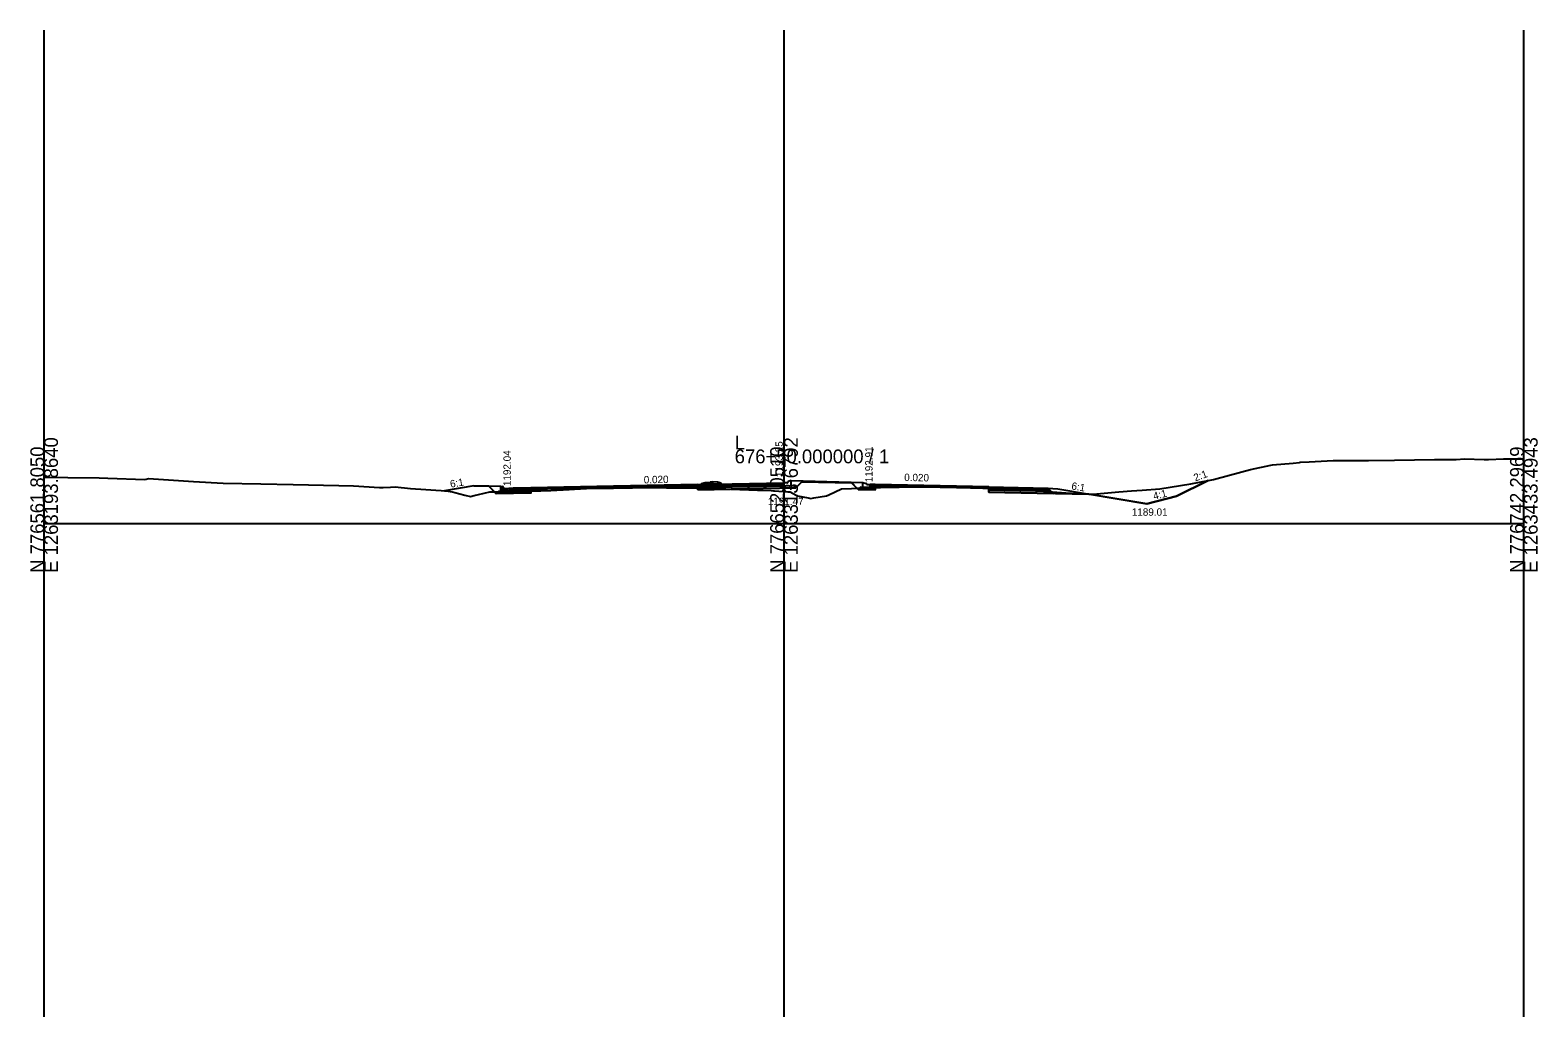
# Model space of a CAD drawing. Extents: x -41 to 1262860, y -100 to 777489.
# Drawn here: x 497.2 to 802.8, y 1605 to 1805 of the extents above; entities that cross this region are included whole.
import ezdxf

# ---------------------------------------------------------------- set-up
doc = ezdxf.new("R2010")
doc.units = 0
for name, color, linetype in [('Exist Cross Section Cell', 7, 'Continuous'), ('Exist XS Center Line Elevation Label', 7, 'Continuous'), ('Exist XS Ground Line', 7, 'Continuous'), ('Prop CMT Pvmt Course 1', 7, 'Continuous'), ('Prop CMT Pvmt Course 4', 7, 'Continuous'), ('Prop CMT Pvmt Surface', 7, 'Continuous'), ('Prop CMT Shld Paved Course 1', 7, 'Continuous'), ('Prop CMT Shld Paved Course 2', 7, 'Continuous'), ('Prop CMT Shld Paved Course 4', 7, 'Continuous'), ('Prop CMT Subgrade Earthwork', 7, 'Continuous'), ('Prop Conc Curb and Gutter', 7, 'Continuous'), ('Prop Conc Island Cover', 7, 'Continuous'), ('Prop XS Ditch Standard Text', 7, 'Continuous'), ('Prop XS Earthwork Shape', 7, 'Continuous'), ('Prop XS Elevation Labels', 7, 'Continuous'), ('Prop XS Exc Vertical Line 1', 7, 'Continuous'), ('Prop XS Exc Vertical Line 2', 7, 'Continuous'), ('Prop XS Exc Vertical Line 3', 7, 'Continuous'), ('Prop XS Finish Grade', 7, 'Continuous'), ('Prop XS Finish Grade Earthwork', 7, 'Continuous'), ('Prop XS Hydro Elevations', 7, 'Continuous'), ('Prop XS SE Text', 7, 'Continuous'), ('Prop XS Side Slope Text', 7, 'Continuous'), ('Scratch_Level_4', 7, 'Continuous'), ('Scratch_Level_6', 7, 'Continuous'), ('Typical Curb CELL', 7, 'Continuous')]:
    doc.layers.add(name, color=color, linetype=linetype)

msp = doc.modelspace()

# ---------------------------------------------------------------- linework, layer by layer
at = {"layer": 'Exist Cross Section Cell'}
for p, q in [((650, 1705), (650, 1720)), ((500, 1705), (650, 1705)), ((650, 1705), (800, 1705))]:
    msp.add_line(p, q, dxfattribs=at)
at = {"layer": 'Exist XS Ground Line'}
msp.add_lwpolyline([(500, 1714.36), (500.81, 1714.36), (504.81, 1714.32), (511.14, 1714.27), (512.93, 1714.2), (520.39, 1713.91), (520.65, 1713.98), (521.15, 1714.12), (530.28, 1713.48), (536.28, 1713.2), (543.91, 1713.04), (550.49, 1712.9), (559.73, 1712.67), (562.71, 1712.64), (568.02, 1712.33), (568.76, 1712.32), (570.23, 1712.39), (571.19, 1712.42), (574.24, 1712.07), (581.51, 1711.62), (582.69, 1711.43), (583.26, 1711.25), (585.31, 1710.74), (586.42, 1710.48), (587.2, 1710.66), (588.08, 1710.88), (590.35, 1711.42), (592.04, 1711.41), (592.94, 1711.39), (593.26, 1711.38), (593.33, 1711.39), (594.01, 1711.41), (598.77, 1711.58), (602.72, 1711.7), (606.45, 1711.87), (607.51, 1711.93), (611.2, 1712.13), (613.45, 1712.17), (623.15, 1712.3), (626.17, 1712.26), (635, 1712.15), (644.65, 1711.78), (647.42, 1711.67), (647.9, 1711.62), (648.06, 1711.6), (650.79, 1711.41), (651.23, 1711.4), (652.49, 1710.74), (652.75, 1710.61), (654.93, 1710.18), (655.47, 1710.08), (656.07, 1710.18), (658.63, 1710.61), (659.09, 1710.83), (661.68, 1712.01), (663.66, 1712.11), (665.82, 1712.22), (673.38, 1712.36), (678.34, 1712.46), (685.26, 1712.32), (690.31, 1712.23), (690.38, 1712.38), (692.66, 1712.25), (702.6, 1711.55), (707.16, 1711.2), (707.82, 1711.17), (708.28, 1711.16), (711.32, 1710.98), (712.69, 1710.94), (717.87, 1711.4), (720.47, 1711.62), (722.65, 1711.79), (726.21, 1712), (732.45, 1713.01), (737.08, 1713.94), (740.33, 1714.81), (744.55, 1715.95), (748.69, 1716.83), (749.02, 1716.86), (753.23, 1717.26), (754.52, 1717.39), (754.59, 1717.4), (754.67, 1717.42), (754.75, 1717.43), (756.45, 1717.49), (761.36, 1717.75), (761.56, 1717.75), (768.53, 1717.78), (773.75, 1717.87), (781.9, 1717.95), (786.25, 1717.99), (787.99, 1718.12), (791.97, 1717.99), (792.83, 1718), (795.85, 1718.12), (797.4, 1718.14), (799.66, 1718.13), (800, 1718.13)], dxfattribs=at)
at = {"layer": 'Prop CMT Pvmt Course 1'}
for p, q in [((595.12, 1711.9), (595.11, 1712.15)), ((598.68, 1711.97), (595.12, 1711.9)), ((632.5, 1712.65), (649.97, 1713)), ((649.97, 1713), (649.97, 1713.25)), ((667.5, 1712.9), (667.5, 1712.65)), ((668.5, 1712.63), (667.5, 1712.65))]:
    msp.add_line(p, q, dxfattribs=at)
for points in [[(598.68, 1712.22), (598.68, 1711.97), (598.68, 1711.97), (615.45, 1712.3), (615.45, 1712.3), (615.45, 1712.3), (632.5, 1712.65), (632.5, 1712.9), (632.5, 1712.9), (615.45, 1712.55), (615.45, 1712.55), (615.45, 1712.55), (598.68, 1712.22), (598.68, 1712.22), (598.68, 1712.22)], [(691.5, 1712.42), (691.5, 1712.42), (668.5, 1712.88), (668.5, 1712.88), (668.5, 1712.88), (668.5, 1712.88), (668.5, 1712.88), (668.5, 1712.63), (668.5, 1712.63), (668.5, 1712.63), (668.5, 1712.63), (691.5, 1712.17), (691.5, 1712.42)]]:
    msp.add_lwpolyline(points, dxfattribs=at)
at = {"layer": 'Prop CMT Pvmt Course 4'}
for p, q in [((592.12, 1711.5), (591.66, 1711.04)), ((598.68, 1711.18), (591.66, 1711.04)), ((592.62, 1711.51), (592.12, 1711.5)), ((598.68, 1711.18), (598.68, 1711.64))]:
    msp.add_line(p, q, dxfattribs=at)
at = {"layer": 'Prop CMT Pvmt Surface'}
for p, q in [((598.68, 1712.22), (595.11, 1712.15)), ((598.68, 1712.22), (632.5, 1712.9)), ((632.5, 1712.9), (649.97, 1713.25)), ((668.5, 1712.88), (667.5, 1712.9)), ((668.5, 1712.88), (691.5, 1712.42)), ((691.5, 1712.42), (703.5, 1712.18))]:
    msp.add_line(p, q, dxfattribs=at)
at = {"layer": 'Prop CMT Shld Paved Course 1'}
for p, q in [((691.5, 1712.42), (691.5, 1712.42)), ((691.5, 1712.42), (691.5, 1712.42)), ((691.5, 1712.42), (691.5, 1712.17)), ((691.5, 1712.17), (691.5, 1712.17)), ((691.5, 1712.17), (703.76, 1711.92)), ((695.5, 1712.34), (695.5, 1712.34)), ((703.76, 1711.92), (703.5, 1712.18))]:
    msp.add_line(p, q, dxfattribs=at)
at = {"layer": 'Prop CMT Shld Paved Course 2'}
for p, q in [((595.12, 1711.56), (595.12, 1711.9)), ((598.77, 1711.97), (598.68, 1711.97)), ((598.68, 1711.97), (598.68, 1711.97)), ((598.68, 1711.97), (598.68, 1711.64)), ((602.72, 1712.05), (598.77, 1711.97)), ((598.77, 1711.97), (598.77, 1711.97)), ((606.45, 1712.12), (602.72, 1712.05)), ((603.29, 1711.73), (606.45, 1711.87)), ((607.51, 1712.15), (606.45, 1712.12)), ((606.45, 1712.12), (606.45, 1712.12)), ((606.45, 1711.87), (607.51, 1711.93)), ((606.45, 1711.87), (606.45, 1711.87)), ((611.2, 1712.22), (607.51, 1712.15)), ((607.51, 1712.15), (607.51, 1712.15)), ((607.51, 1711.93), (611.2, 1712.13)), ((607.51, 1711.93), (607.51, 1711.93)), ((613.45, 1712.26), (611.2, 1712.22)), ((611.2, 1712.22), (611.2, 1712.22)), ((611.2, 1712.13), (613.45, 1712.17)), ((611.2, 1712.13), (611.2, 1712.13)), ((615.45, 1712.3), (613.45, 1712.26)), ((613.45, 1712.26), (613.45, 1712.26)), ((613.45, 1712.17), (615.45, 1712.19)), ((613.45, 1712.17), (613.45, 1712.17)), ((623.15, 1712.46), (615.45, 1712.3)), ((615.45, 1712.19), (623.15, 1712.3)), ((626.17, 1712.52), (623.15, 1712.46)), ((623.15, 1712.46), (623.15, 1712.46)), ((623.15, 1712.46), (623.15, 1712.46)), ((623.15, 1712.3), (623.15, 1712.3)), ((623.15, 1712.3), (623.15, 1712.3)), ((623.15, 1712.3), (626.17, 1712.26)), ((632.5, 1712.65), (626.17, 1712.52)), ((626.17, 1712.52), (626.17, 1712.52)), ((626.17, 1712.52), (626.17, 1712.52)), ((626.17, 1712.26), (626.17, 1712.26)), ((626.17, 1712.26), (628.42, 1712.23)), ((628.42, 1712.23), (632.5, 1712.31)), ((632.5, 1712.31), (649.97, 1712.66)), ((632.5, 1712.31), (632.5, 1712.65)), ((632.5, 1712.65), (632.5, 1712.65)), ((632.5, 1712.31), (632.5, 1712.31)), ((649.97, 1713), (649.97, 1712.66)), ((667.5, 1712.31), (667.5, 1712.65)), ((668.5, 1712.29), (667.5, 1712.31)), ((668.5, 1712.29), (668.5, 1712.63)), ((668.5, 1712.63), (668.5, 1712.63)), ((668.5, 1712.63), (668.5, 1712.63)), ((668.5, 1712.63), (668.5, 1712.63)), ((668.5, 1712.63), (673.38, 1712.53)), ((669.01, 1712.28), (668.5, 1712.29)), ((668.5, 1712.29), (668.5, 1712.29)), ((668.5, 1712.29), (668.5, 1712.29)), ((673.38, 1712.36), (669.01, 1712.28)), ((669.01, 1712.28), (669.01, 1712.28)), ((673.38, 1712.53), (673.38, 1712.53)), ((673.38, 1712.53), (678.34, 1712.43)), ((677.51, 1712.45), (673.38, 1712.36)), ((673.38, 1712.36), (673.38, 1712.36)), ((678.34, 1712.43), (677.51, 1712.45)), ((677.51, 1712.45), (677.51, 1712.45)), ((685.26, 1712.29), (678.34, 1712.43)), ((678.34, 1712.43), (685.26, 1712.29)), ((690.31, 1712.19), (685.26, 1712.29)), ((685.26, 1712.29), (685.26, 1712.29)), ((685.26, 1712.29), (685.26, 1712.29)), ((685.26, 1712.29), (690.31, 1712.19)), ((690.38, 1712.19), (690.31, 1712.19)), ((690.31, 1712.19), (690.31, 1712.19)), ((690.31, 1712.19), (690.31, 1712.19)), ((690.31, 1712.19), (690.38, 1712.19)), ((691.5, 1712.17), (690.38, 1712.19)), ((690.38, 1712.19), (690.38, 1712.19)), ((690.38, 1712.19), (690.38, 1712.19)), ((690.38, 1712.19), (691.5, 1712.17)), ((691.5, 1712.17), (691.5, 1712.17)), ((691.5, 1712.17), (691.5, 1712.17)), ((691.5, 1712.17), (691.5, 1711.83)), ((691.5, 1712.17), (691.5, 1712.17)), ((691.5, 1712.17), (691.5, 1712.17)), ((691.5, 1711.83), (691.5, 1711.83)), ((691.5, 1711.83), (704.1, 1711.58)), ((695.76, 1712.08), (695.76, 1712.08)), ((704.1, 1711.58), (703.76, 1711.92)), ((598.68, 1711.64), (595.12, 1711.56)), ((598.68, 1711.64), (598.77, 1711.64)), ((598.77, 1711.64), (602.72, 1711.72)), ((598.77, 1711.64), (598.77, 1711.64)), ((602.72, 1711.72), (603.29, 1711.73)), ((602.72, 1711.72), (602.72, 1711.72))]:
    msp.add_line(p, q, dxfattribs=at)
at = {"layer": 'Prop CMT Shld Paved Course 4'}
for p, q in [((628.42, 1712.23), (632.5, 1712.18)), ((632.5, 1711.85), (632.5, 1712.31)), ((632.5, 1711.85), (652.42, 1712.25)), ((649.97, 1712.66), (651.97, 1712.7)), ((651.97, 1712.7), (652.42, 1712.25)), ((665.5, 1712.35), (665.05, 1711.9)), ((668.5, 1711.83), (665.05, 1711.9)), ((667.5, 1712.31), (665.5, 1712.35)), ((668.5, 1711.83), (668.5, 1712.29)), ((669.01, 1712.28), (668.5, 1712.27)), ((691.5, 1711.83), (691.5, 1711.83)), ((691.5, 1711.83), (691.5, 1711.83)), ((691.5, 1711.83), (691.5, 1711.37)), ((598.77, 1711.58), (598.68, 1711.58)), ((598.77, 1711.58), (602.72, 1711.7)), ((603.29, 1711.73), (602.72, 1711.7)), ((691.5, 1711.37), (704.56, 1711.11)), ((696.1, 1711.74), (696.1, 1711.74)), ((696.6, 1711.73), (696.6, 1711.73)), ((704.56, 1711.11), (704.1, 1711.58))]:
    msp.add_line(p, q, dxfattribs=at)
at = {"layer": 'Prop CMT Subgrade Earthwork'}
for p, q in [((591.66, 1711.04), (590.13, 1712.56)), ((632.5, 1711.85), (652.42, 1712.25)), ((632.5, 1711.85), (632.5, 1712.18)), ((652.42, 1712.25), (653.81, 1713.64)), ((665.05, 1711.9), (663.55, 1713.4)), ((665.05, 1711.9), (668.5, 1711.83)), ((668.5, 1711.83), (668.5, 1712.27)), ((691.5, 1712.32), (691.5, 1711.37)), ((598.68, 1711.18), (591.66, 1711.04)), ((598.68, 1711.58), (598.68, 1711.18)), ((691.5, 1711.37), (711.78, 1710.97))]:
    msp.add_line(p, q, dxfattribs=at)
at = {"layer": 'Prop Conc Curb and Gutter'}
for p, q in [((633.25, 1712.91), (633.26, 1713.08)), ((633.25, 1712.91), (633.25, 1712.91)), ((633.25, 1712.91), (633.25, 1712.79)), ((635.01, 1712.91), (633.25, 1712.91)), ((633.25, 1712.91), (633.25, 1712.91)), ((633.25, 1712.79), (633.25, 1712.79)), ((633.25, 1712.79), (635.01, 1712.79)), ((633.26, 1713.08), (634.01, 1713.33)), ((633.26, 1713.08), (633.26, 1713.08)), ((634.01, 1713.33), (635.01, 1713.35)), ((634.01, 1713.33), (634.01, 1713.33)), ((635.01, 1713.35), (635.01, 1712.91)), ((635.01, 1712.79), (635.01, 1712.91)), ((635.01, 1712.91), (635.01, 1712.91)), ((635.01, 1712.79), (635.01, 1712.79)), ((635.01, 1712.79), (635.01, 1712.79)), ((636.49, 1713.41), (635.49, 1713.43)), ((635.49, 1713.43), (635.49, 1712.99)), ((637.25, 1712.99), (635.49, 1712.99)), ((635.49, 1712.99), (635.49, 1712.87)), ((635.49, 1712.99), (635.49, 1712.99)), ((635.49, 1712.87), (635.49, 1712.87)), ((635.49, 1712.87), (637.25, 1712.87)), ((637.24, 1713.16), (636.49, 1713.41)), ((636.49, 1713.41), (636.49, 1713.41)), ((637.25, 1712.99), (637.24, 1713.16)), ((637.24, 1713.16), (637.24, 1713.16)), ((637.25, 1712.87), (637.25, 1712.99)), ((637.25, 1712.99), (637.25, 1712.99)), ((637.25, 1712.99), (637.25, 1712.99)), ((637.25, 1712.87), (637.25, 1712.87)), ((637.25, 1712.87), (637.25, 1712.87)), ((650.66, 1713.26), (649.97, 1713.25)), ((649.97, 1713.25), (649.97, 1712.66)), ((649.97, 1712.66), (651.47, 1712.69)), ((650.72, 1713.34), (650.72, 1713.32)), ((651.47, 1713.69), (650.82, 1713.48)), ((651.47, 1712.69), (651.47, 1713.69)), ((651.47, 1712.69), (651.47, 1712.69)), ((666, 1713.34), (666.65, 1713.13)), ((666, 1712.34), (666, 1713.34)), ((667.5, 1712.31), (666, 1712.34)), ((666.75, 1712.99), (666.75, 1712.97)), ((666.81, 1712.91), (667.5, 1712.9)), ((667.5, 1712.31), (667.5, 1712.9))]:
    msp.add_line(p, q, dxfattribs=at)
for centre, radius, start, end in [((650.66, 1713.32), 0.0625, 271.1458, 360), ((650.87, 1713.34), 0.146, 108.435, 180), ((666.6, 1712.99), 0.146, 0, 71.565), ((666.81, 1712.97), 0.0625, 180, 268.8542)]:
    msp.add_arc(centre, radius, start, end, dxfattribs=at)
at = {"layer": 'Prop Conc Island Cover'}
for p, q in [((635.49, 1713.43), (635.01, 1713.35)), ((635.01, 1713.35), (635.01, 1713.1)), ((635.49, 1713.17), (635.01, 1713.09)), ((635.49, 1713.18), (635.49, 1713.43)), ((635.49, 1713.43), (635.49, 1713.43)), ((635.49, 1713.18), (635.49, 1713.18)), ((651.47, 1713.69), (666, 1713.34)), ((651.47, 1713.43), (651.47, 1713.43))]:
    msp.add_line(p, q, dxfattribs=at)
at = {"layer": 'Prop XS Earthwork Shape'}
for points in [[(586.42, 1710.48), (587.2, 1710.66), (588.08, 1710.88), (590.35, 1711.42), (591.28, 1711.42), (590.13, 1712.56), (587.1, 1712.62), (581.18, 1711.64), (581.51, 1711.62), (582.69, 1711.43), (583.26, 1711.25), (585.31, 1710.74)], [(632.5, 1711.85), (632.5, 1712.18), (635, 1712.15), (639.26, 1711.99)], [(663.66, 1712.11), (664.78, 1712.17), (663.81, 1713.15), (653.56, 1713.39), (652.42, 1712.25), (639.26, 1711.99), (644.65, 1711.78), (647.42, 1711.67), (647.9, 1711.62), (648.06, 1711.6), (650.79, 1711.41), (651.23, 1711.4), (652.49, 1710.74), (652.75, 1710.61), (654.93, 1710.18), (655.47, 1710.08), (656.07, 1710.18), (658.63, 1710.61), (659.09, 1710.83), (661.68, 1712.01)], [(665.05, 1711.9), (664.78, 1712.17), (665.82, 1712.22), (668.5, 1712.27), (668.5, 1711.83)], [(702.6, 1711.55), (704.25, 1711.42), (704.56, 1711.11), (691.5, 1711.37), (691.5, 1712.32), (692.66, 1712.25)], [(720.47, 1711.62), (722.65, 1711.79), (726.21, 1712), (732.45, 1713.01), (736.03, 1713.73), (729.6, 1710.52), (723.56, 1709.01), (711.78, 1710.97), (712.69, 1710.94), (717.87, 1711.4)], [(593.33, 1711.39), (594.01, 1711.41), (598.68, 1711.58), (598.68, 1711.18), (591.66, 1711.04), (591.28, 1711.42), (592.04, 1711.41), (592.94, 1711.39), (593.26, 1711.38)], [(707.82, 1711.17), (708.28, 1711.16), (711.32, 1710.98), (711.78, 1710.97), (704.56, 1711.11), (704.25, 1711.42), (707.16, 1711.2)]]:
    msp.add_lwpolyline(points, close=True, dxfattribs=at)
at = {"layer": 'Prop XS Exc Vertical Line 1'}
msp.add_line((500, 1605), (500, 1805), dxfattribs=at)
at = {"layer": 'Prop XS Exc Vertical Line 2'}
msp.add_line((650, 1605), (650, 1805), dxfattribs=at)
at = {"layer": 'Prop XS Exc Vertical Line 3'}
msp.add_line((800, 1605), (800, 1805), dxfattribs=at)
at = {"layer": 'Prop XS Finish Grade'}
for p, q in [((587.1, 1712.62), (581.18, 1711.64)), ((587.1, 1712.62), (590.13, 1712.56)), ((703.5, 1712.18), (705.5, 1712.02)), ((703.5, 1712.18), (704.56, 1711.11)), ((705.5, 1712.02), (723.56, 1709.01)), ((729.6, 1710.52), (736.03, 1713.73)), ((723.56, 1709.01), (729.6, 1710.52))]:
    msp.add_line(p, q, dxfattribs=at)
at = {"layer": 'Prop XS Finish Grade Earthwork'}
msp.add_line((592.6, 1712.51), (590.13, 1712.56), dxfattribs=at)
at = {"layer": 'Scratch_Level_4'}
msp.add_line((800, 1605), (800, 1805), dxfattribs=at)
at = {"layer": 'Scratch_Level_6'}
msp.add_line((500, 1605), (500, 1805), dxfattribs=at)
at = {"layer": 'Typical Curb CELL'}
for p, q in [((592.6, 1712.51), (592.86, 1712.52)), ((592.62, 1711.51), (592.6, 1712.51)), ((592.65, 1712.14), (592.8, 1712.19)), ((592.79, 1712.09), (592.65, 1712.14)), ((592.78, 1711.82), (592.68, 1711.74)), ((592.85, 1711.71), (592.78, 1711.82)), ((592.8, 1712.19), (592.79, 1712.09)), ((593.11, 1712.27), (593.11, 1712.29)), ((595.11, 1712.15), (593.36, 1712.04)), ((593.52, 1711.89), (593.49, 1711.78)), ((593.61, 1711.77), (593.52, 1711.89)), ((594.03, 1711.85), (593.93, 1711.77)), ((594.09, 1711.73), (594.03, 1711.85)), ((594.77, 1711.92), (594.74, 1711.8)), ((594.86, 1711.8), (594.77, 1711.92)), ((595.12, 1711.56), (595.11, 1712.15)), ((592.62, 1711.51), (595.12, 1711.56)), ((592.68, 1711.74), (592.85, 1711.71)), ((593.49, 1711.78), (593.61, 1711.77)), ((593.93, 1711.77), (594.09, 1711.73)), ((594.74, 1711.8), (594.86, 1711.8))]:
    msp.add_line(p, q, dxfattribs=at)
for centre in [(592.62, 1712.4), (592.67, 1712.22), (592.78, 1711.95), (592.84, 1712.44), (592.9, 1712.01), (593.08, 1711.84), (593.15, 1712.04), (593.17, 1711.99), (593.2, 1711.82), (593.35, 1711.91), (593.38, 1712.01), (593.57, 1711.97), (593.67, 1712.02), (593.78, 1711.94), (593.83, 1711.97), (593.85, 1711.88), (594.03, 1711.98), (594.14, 1712.03), (594.32, 1711.87), (594.4, 1712.06), (594.42, 1712.01), (594.45, 1711.84), (594.6, 1711.93), (594.62, 1712.03), (594.77, 1712.1), (594.82, 1712), (594.91, 1712.09), (595.03, 1711.96), (595.08, 1712), (595.1, 1711.9), (592.77, 1711.56), (592.94, 1711.61), (593.12, 1711.55), (593.17, 1711.66), (593.29, 1711.58), (593.49, 1711.61), (593.65, 1711.54), (593.7, 1711.78), (593.8, 1711.73), (593.86, 1711.57), (594.02, 1711.59), (594.19, 1711.63), (594.37, 1711.57), (594.42, 1711.69), (594.54, 1711.6), (594.74, 1711.63), (594.9, 1711.57), (594.95, 1711.8), (595.05, 1711.76), (595.11, 1711.59)]:
    msp.add_circle(centre, 0.00802, dxfattribs=at)
for centre, start, end in [((592.87, 1712.28), 1.1458, 91.1458), ((593.35, 1712.28), 181.1458, 273.5302)]:
    msp.add_arc(centre, 0.24, start, end, dxfattribs=at)

# ---------------------------------------------------------------- texts
at = {"layer": 'Exist Cross Section Cell'}
for s, p in [('E 1263193.8640', (502.8, 1695)), ('E 1263313.6792', (652.8, 1695)), ('E 1263433.4943', (802.8, 1695)), ('N 776561.8050', (500, 1695)), ('N 776652.0510', (650, 1695)), ('N 776742.2969', (800, 1695))]:
    msp.add_text(s, height=2.8, rotation=90, dxfattribs=at).set_placement(p)
for s, p in [('L', (640, 1720)), ('676+50.000000 / 1', (640, 1717.2))]:
    msp.add_text(s, height=2.8, dxfattribs=at).set_placement(p)
at = {"layer": 'Exist XS Center Line Elevation Label'}
msp.add_text('1191.47', height=1.5, dxfattribs=at).set_placement((646.72, 1708.72))
at = {"layer": 'Prop XS Ditch Standard Text'}
msp.add_text('1189.01', height=1.5, dxfattribs=at).set_placement((720.52, 1706.57))
at = {"layer": 'Prop XS Elevation Labels'}
for s, p in [('1192.04', (594.61, 1712.58)), ('1192.91', (667.96, 1713.37))]:
    msp.add_text(s, height=1.5, rotation=90, dxfattribs=at).set_placement(p)
at = {"layer": 'Prop XS Hydro Elevations'}
msp.add_text('1193.25', height=1.5, rotation=90, dxfattribs=at).set_placement((649.75, 1714.42))
at = {"layer": 'Prop XS SE Text'}
for rotation, p in [(358.8542, (674.36, 1713.62)), (1.1458, (621.58, 1713.12))]:
    msp.add_text('0.020', height=1.5, rotation=rotation, dxfattribs=at).set_placement(p)
at = {"layer": 'Prop XS Side Slope Text'}
for s, rotation, p in [('2:1', 20.1493, (733.38, 1713.5)), ('6:1', 9.4623, (582.42, 1712.25)), ('6:1', 350.5377, (708.19, 1711.92)), ('4:1', 14.0362, (725.04, 1709.79))]:
    msp.add_text(s, height=1.5, rotation=rotation, dxfattribs=at).set_placement(p)

doc.saveas('drawing.dxf')
